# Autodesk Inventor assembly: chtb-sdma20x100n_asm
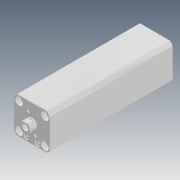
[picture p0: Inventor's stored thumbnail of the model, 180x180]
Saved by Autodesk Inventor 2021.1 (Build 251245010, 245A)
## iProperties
Created: 2018-05
Part Number: chtb-sdma20x100n_asm
Description: STEP AP214
Document SubType Name: Assembly
Designer: user
Title: chtb-sdma20x100n_asm.STEP
Revision Number: ÈÎºÎ
Sending System: SolidWorks 2016
Preprocessor: SwSTEP 2.0
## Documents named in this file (5)
- D:\Vault_2016\Projekty\Clamptek\Hydraulic\CHTB\CHTB-20\Inventor\CHTB-SDMA20x100N\chtb-sdma20x100n_asm.iam
- D:\Vault_2016\Projekty\Clamptek\Hydraulic\CHTB\CHTB-20\Inventor\CHTB-SDMA20x100N\CHTB-SDMA20X100NBT.ipt
- D:\Vault_2016\Projekty\Clamptek\Hydraulic\CHTB\CHTB-20\Inventor\CHTB-SDMA20x100N\CHTB-SDMA20X100NHSG.ipt
- D:\Vault_2016\Projekty\Clamptek\Hydraulic\CHTB\CHTB-20\Inventor\CHTB-SDMA20x100N\QG_3.ipt
- D:\Vault_2016\Projekty\Clamptek\Hydraulic\CHTB\CHTB-20\Inventor\CHTB-SDMA20x100N\socket set screw flat point_iso_ISO 4026 - M5 x 5-N.ipt
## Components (5 placed, 5 different names)
1. CHTB-SDMA20X100NBT_1
2. CHTB-SDMA20X100NHSG_2
3. QG_3_3
4. socket set screw flat point_iso_ISO 4026 - M5 x 5-N_4
5. socket set screw flat point_iso_ISO 4026 - M5 x 5-N_5
